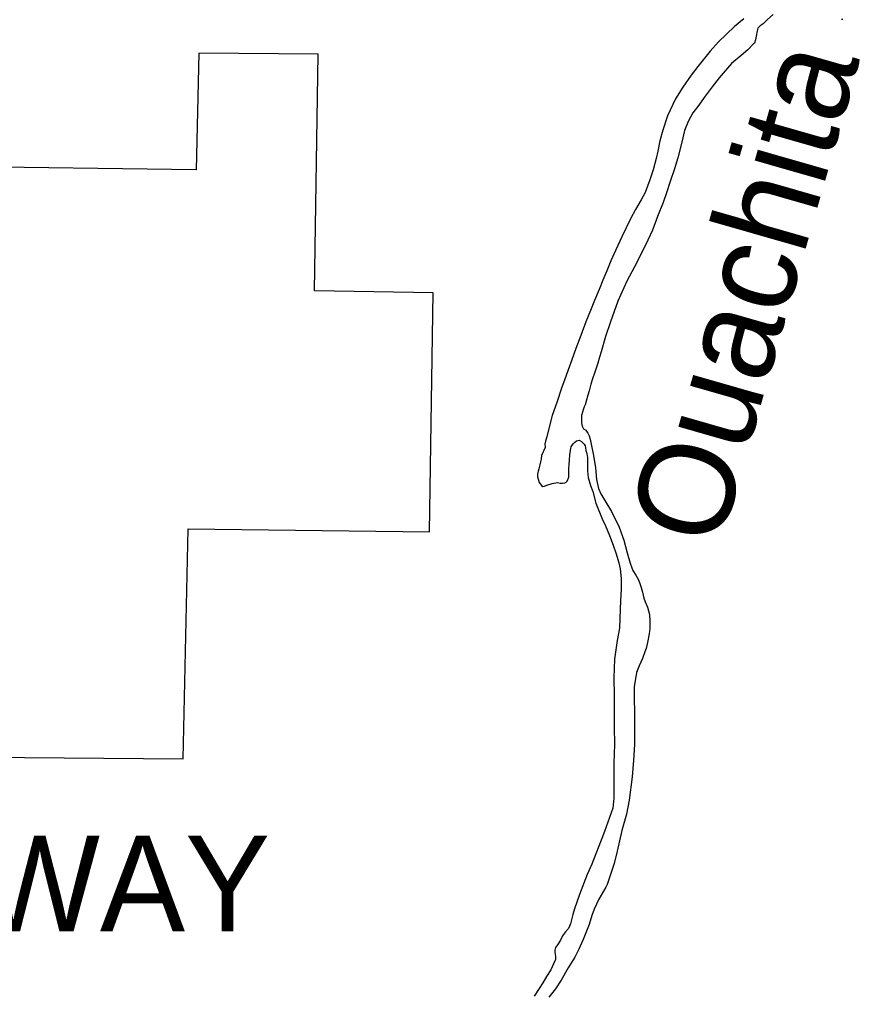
# Model space of a CAD drawing. Extents: x 1373862 to 1377080, y 1164775 to 1170415.
# Drawn here: x 1374487.3 to 1374533.8, y 1170097.4 to 1170151.1 of the extents above; entities that cross this region are included whole.
import ezdxf

# ---------------------------------------------------------------- set-up
doc = ezdxf.new("R2010")
doc.units = 0
doc.layers.add('Default', color=7, linetype='Continuous')

msp = doc.modelspace()

# ---------------------------------------------------------------- linework, layer by layer
at = {"layer": 'Default'}
for points in [[(1374529.043, 1170151.374), (1374528.726, 1170151.091), (1374528.488, 1170150.859), (1374528.319, 1170150.737), (1374528.181, 1170150.606), (1374528.142, 1170150.465), (1374528.104, 1170150.165), (1374528.066, 1170149.964), (1374527.998, 1170149.783), (1374527.948, 1170149.743), (1374527.641, 1170149.42), (1374527.265, 1170149.106), (1374526.739, 1170148.661), (1374526.057, 1170147.854), (1374525.662, 1170147.36), (1374525.217, 1170146.775), (1374524.921, 1170146.352), (1374524.585, 1170145.918), (1374524.329, 1170145.446), (1374524.134, 1170144.953), (1374523.979, 1170144.311), (1374523.757, 1170143.438), (1374523.582, 1170142.835), (1374523.328, 1170142.122), (1374523.134, 1170141.5), (1374522.949, 1170140.957), (1374522.635, 1170140.184), (1374522.352, 1170139.43), (1374522.097, 1170138.887), (1374521.714, 1170138.083), (1374521.36, 1170137.399), (1374520.947, 1170136.614), (1374520.437, 1170135.498), (1374520.027, 1170134.363), (1374519.755, 1170133.539), (1374519.522, 1170132.696), (1374519.425, 1170132.405), (1374519.328, 1170132.064), (1374519.162, 1170131.571), (1374519.045, 1170131.2), (1374518.948, 1170130.909), (1374518.851, 1170130.537), (1374518.783, 1170130.296), (1374518.686, 1170129.975), (1374518.628, 1170129.764), (1374518.579, 1170129.654), (1374518.53, 1170129.483), (1374518.491, 1170129.352), (1374518.423, 1170129.172), (1374518.434, 1170129.022), (1374518.434, 1170128.961), (1374518.426, 1170128.791), (1374518.447, 1170128.661), (1374518.488, 1170128.541), (1374518.549, 1170128.442), (1374518.669, 1170128.363), (1374518.78, 1170128.203), (1374518.851, 1170128.054), (1374518.903, 1170127.874), (1374518.965, 1170127.584), (1374519.09, 1170126.954), (1374519.215, 1170126.274), (1374519.26, 1170125.634), (1374519.364, 1170125.144), (1374519.507, 1170124.835), (1374519.78, 1170124.386), (1374520.094, 1170123.868), (1374520.51, 1170122.991), (1374520.766, 1170122.272)], [(1374527.418, 1170151.12), (1374526.902, 1170150.695), (1374526.011, 1170149.846), (1374525.545, 1170149.342), (1374524.873, 1170148.495), (1374524.508, 1170148.011), (1374524.044, 1170147.346), (1374523.64, 1170146.701), (1374523.483, 1170146.39), (1374523.189, 1170145.756), (1374522.926, 1170144.963), (1374522.761, 1170144.381), (1374522.656, 1170143.799), (1374522.569, 1170143.398), (1374522.394, 1170142.775), (1374522.219, 1170142.213), (1374521.946, 1170141.52), (1374521.729, 1170141.107), (1374521.424, 1170140.584), (1374521.149, 1170140.051), (1374520.668, 1170139.055), (1374520.324, 1170138.341), (1374520.06, 1170137.738), (1374519.825, 1170137.185), (1374519.609, 1170136.663), (1374519.404, 1170136.15), (1374519.149, 1170135.547), (1374518.924, 1170134.984), (1374518.68, 1170134.361), (1374518.386, 1170133.598), (1374518.123, 1170132.884), (1374517.888, 1170132.251), (1374517.693, 1170131.709), (1374517.488, 1170131.126), (1374517.342, 1170130.745), (1374517.059, 1170129.891), (1374516.815, 1170129.168), (1374516.621, 1170128.465), (1374516.505, 1170128.004), (1374516.448, 1170127.753), (1374516.409, 1170127.582), (1374516.43, 1170127.412), (1374516.225, 1170126.96), (1374516.196, 1170126.759), (1374516.167, 1170126.609), (1374516.129, 1170126.448), (1374516.071, 1170126.227), (1374516.032, 1170126.087), (1374515.993, 1170125.926), (1374516.005, 1170125.776), (1374516.056, 1170125.606), (1374516.097, 1170125.476), (1374516.158, 1170125.367), (1374516.218, 1170125.297), (1374516.289, 1170125.238), (1374516.388, 1170125.259), (1374516.517, 1170125.32), (1374516.806, 1170125.412), (1374517.105, 1170125.465), (1374517.255, 1170125.436), (1374517.385, 1170125.427), (1374517.505, 1170125.448), (1374517.584, 1170125.489), (1374517.634, 1170125.55), (1374517.722, 1170125.761), (1374517.73, 1170125.951), (1374517.729, 1170126.131), (1374517.738, 1170126.242), (1374517.756, 1170126.462), (1374517.764, 1170126.702)], [(1374532.889, 1170151.097), (1374532.869, 1170151.087), (1374532.859, 1170151.087), (1374532.809, 1170151.096)], [(1374497.263, 1170149.233), (1374497.116, 1170142.765), (1374483.492, 1170142.957), (1374483.483, 1170136.357), (1374483.466, 1170123.183), (1374458.594, 1170124.258)], [(1374510.029, 1170122.729), (1374510.232, 1170135.97), (1374503.662, 1170136.071), (1374503.863, 1170149.167), (1374497.263, 1170149.233)], [(1374517.764, 1170126.702), (1374517.792, 1170126.993), (1374517.83, 1170127.244), (1374517.849, 1170127.364), (1374517.868, 1170127.434), (1374517.976, 1170127.606), (1374518.065, 1170127.706), (1374518.155, 1170127.767), (1374518.304, 1170127.809), (1374518.425, 1170127.74), (1374518.585, 1170127.591), (1374518.626, 1170127.491), (1374518.657, 1170127.381), (1374518.678, 1170127.241), (1374518.729, 1170127.071), (1374518.761, 1170126.851), (1374518.764, 1170126.571), (1374518.767, 1170126.12), (1374518.8, 1170125.75), (1374518.934, 1170125.31), (1374519.056, 1170124.961), (1374519.231, 1170124.322), (1374519.578, 1170123.453), (1374519.761, 1170123.064), (1374519.975, 1170122.535), (1374520.179, 1170122.006), (1374520.342, 1170121.527), (1374520.496, 1170121.018), (1374520.569, 1170120.698), (1374520.623, 1170120.147), (1374520.618, 1170119.567), (1374520.593, 1170118.935), (1374520.577, 1170118.445), (1374520.561, 1170117.944), (1374520.526, 1170117.413), (1374520.402, 1170116.721), (1374520.261, 1170115.688), (1374520.229, 1170114.666), (1374520.237, 1170113.685), (1374520.247, 1170112.513), (1374520.241, 1170111.932), (1374520.249, 1170110.971), (1374520.218, 1170109.929), (1374520.225, 1170109.018), (1374520.229, 1170108.567), (1374520.224, 1170108.007), (1374520.168, 1170107.445), (1374519.71, 1170106.16), (1374519.553, 1170105.768), (1374519.348, 1170105.255), (1374518.996, 1170104.351), (1374518.741, 1170103.778), (1374518.321, 1170102.673), (1374518.038, 1170101.879), (1374517.96, 1170101.558), (1374517.825, 1170101.046), (1374517.707, 1170100.795), (1374517.549, 1170100.593), (1374517.381, 1170100.381), (1374517.273, 1170100.15), (1374517.105, 1170099.888), (1374516.997, 1170099.727), (1374516.958, 1170099.587), (1374516.949, 1170099.486), (1374516.98, 1170099.356), (1374517.001, 1170099.236), (1374516.992, 1170099.076), (1374516.884, 1170098.835), (1374516.727, 1170098.503), (1374516.501, 1170098.121), (1374516.294, 1170097.788), (1374516.087, 1170097.466), (1374515.821, 1170097.033)], [(1374476.061, 1170076.786), (1374476.165, 1170084.065), (1374469.57, 1170084.16), (1374469.765, 1170097.2), (1374469.959, 1170110.602), (1374483.197, 1170110.288), (1374496.398, 1170110.184), (1374496.663, 1170122.897), (1374510.029, 1170122.729)], [(1374520.766, 1170122.272), (1374520.961, 1170121.582), (1374521.115, 1170121.013), (1374521.207, 1170120.743), (1374521.278, 1170120.604), (1374521.43, 1170120.345), (1374521.582, 1170120.076), (1374521.664, 1170119.876), (1374521.726, 1170119.656), (1374521.798, 1170119.396), (1374521.88, 1170119.067), (1374521.962, 1170118.857), (1374522.084, 1170118.568), (1374522.187, 1170118.158), (1374522.22, 1170117.778), (1374522.203, 1170117.387), (1374522.176, 1170117.086), (1374522.08, 1170116.605), (1374522.003, 1170116.274), (1374521.934, 1170116.093), (1374521.808, 1170115.721), (1374521.631, 1170115.329), (1374521.475, 1170114.947), (1374521.341, 1170114.155), (1374521.337, 1170113.514), (1374521.363, 1170112.743), (1374521.362, 1170111.612), (1374521.357, 1170110.971), (1374521.315, 1170110.109), (1374521.242, 1170109.177), (1374521.073, 1170107.884), (1374520.92, 1170107.111), (1374520.658, 1170106.208), (1374520.407, 1170105.074), (1374520.243, 1170104.382), (1374520, 1170103.668), (1374519.844, 1170103.226), (1374519.775, 1170103.076), (1374519.391, 1170102.411), (1374519.126, 1170101.858), (1374519.009, 1170101.507), (1374518.853, 1170101.005), (1374518.521, 1170100.181), (1374518.286, 1170099.648), (1374518.06, 1170099.205), (1374517.695, 1170098.601), (1374517.311, 1170097.927), (1374516.996, 1170097.454), (1374516.62, 1170096.98)]]:
    msp.add_lwpolyline(points, dxfattribs=at)

# ---------------------------------------------------------------- texts
msp.add_text('Ouachita', height=5.28, rotation=74, dxfattribs=at).set_placement((1374526.049, 1170121.719))
msp.add_text('MIDWAY', height=5.28, dxfattribs=at).set_placement((1374472.18, 1170100.637))

doc.saveas('drawing.dxf')
